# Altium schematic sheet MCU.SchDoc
size 558 x 431 mm; DocumentNumber: 4; SheetNumber: 4; SheetTotal: 4; PageSetup: Record=PageOptions|CenterHorizontal=True|CenterVertical=True|PrintScale=0.89|XCorrection=1.00|YCorrection=1.00|PrintKind=0|BorderSize=5000000|LeftOffset=0|BottomOffset=0|Orientation=2|PaperLength=1000|PaperWidth=1000|Scale=100|PaperSource=15|PrintQuality=600|MediaType=1|DitherType=10|PaperKind=A4|PrintScaleMode=1
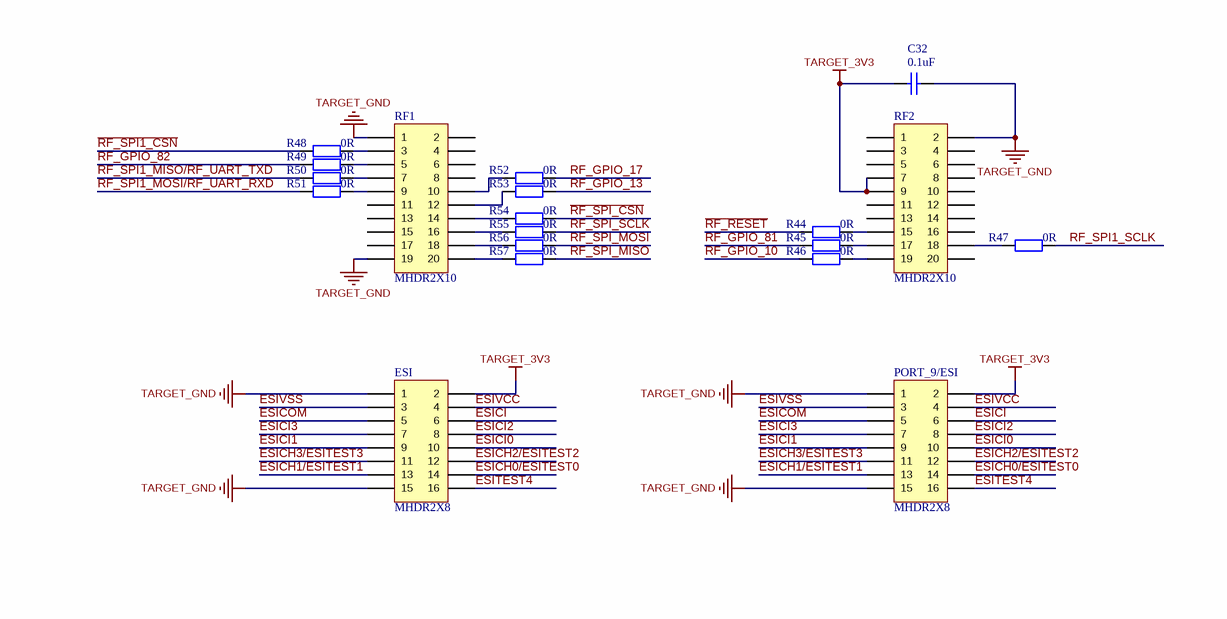
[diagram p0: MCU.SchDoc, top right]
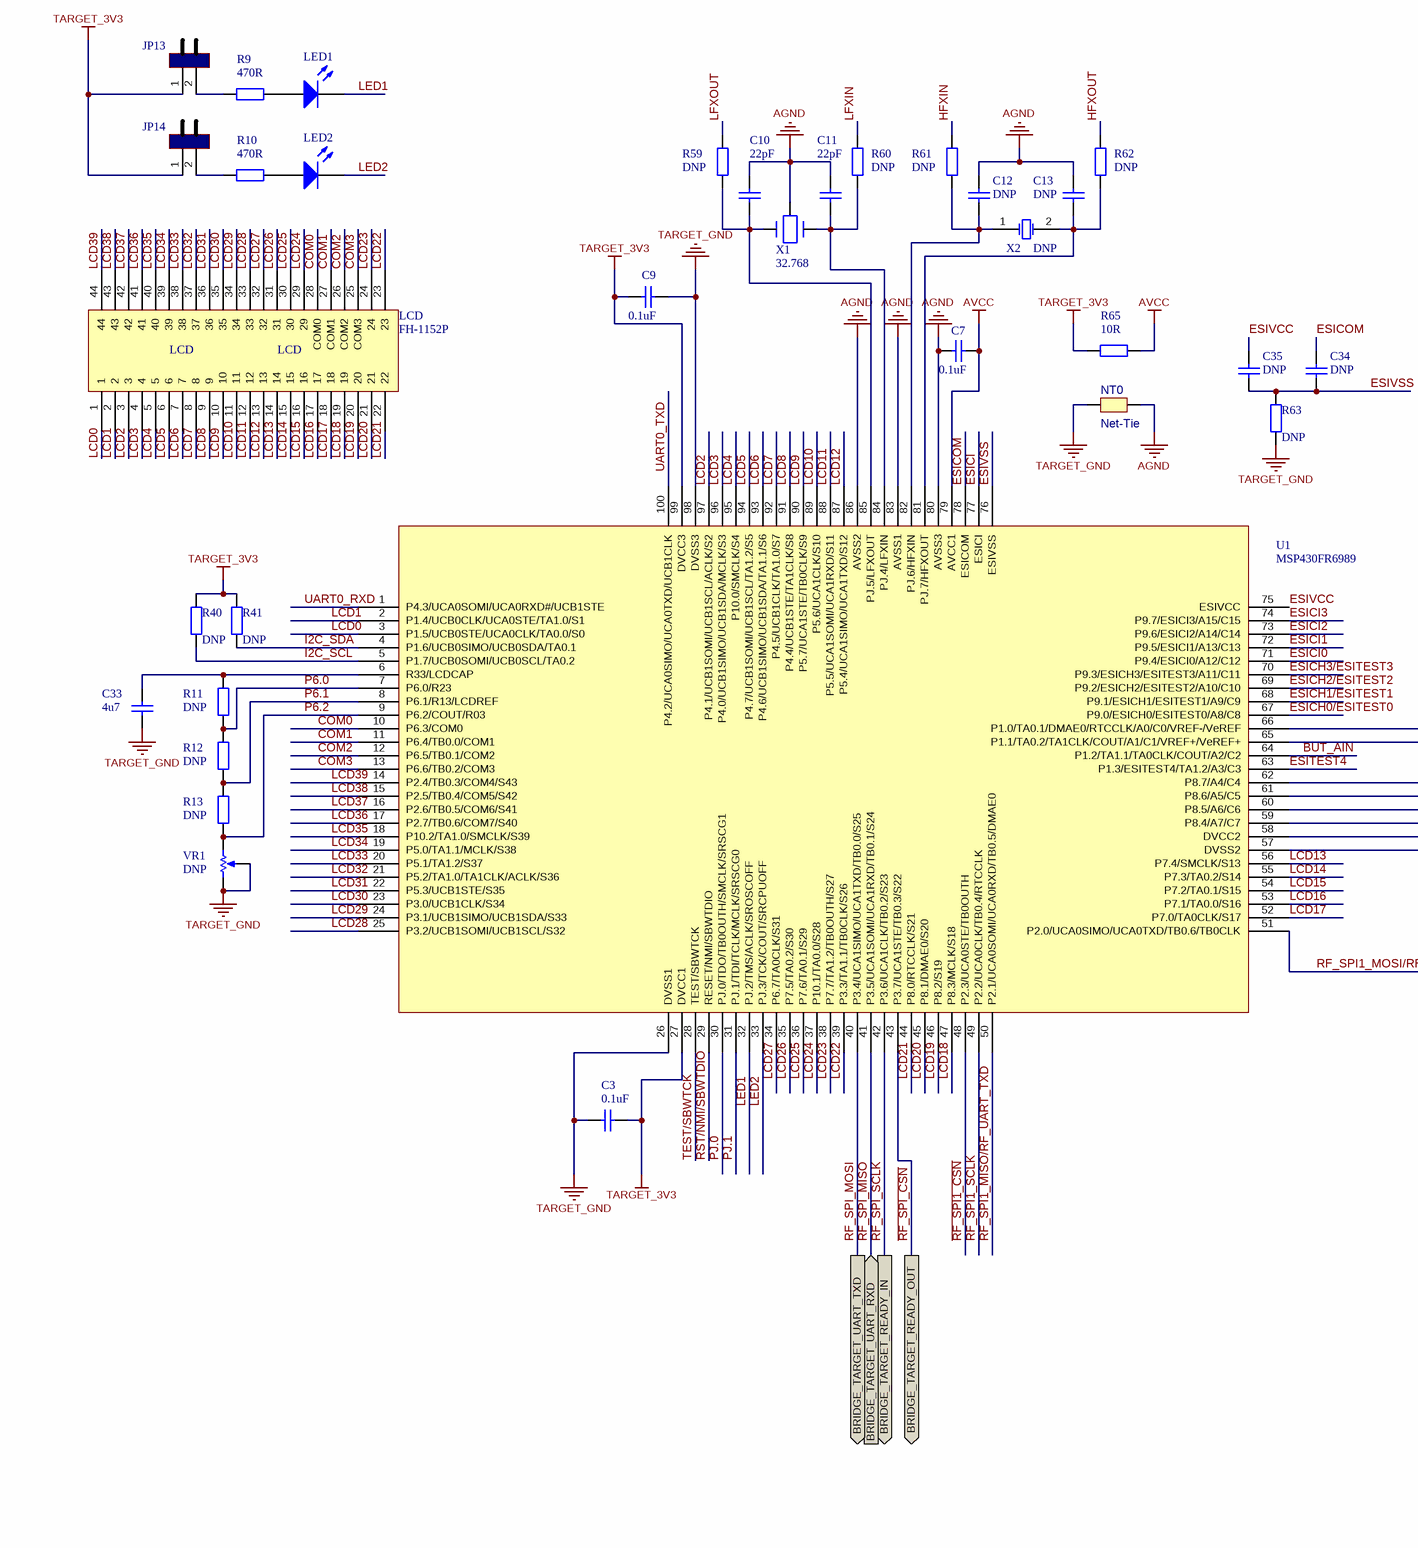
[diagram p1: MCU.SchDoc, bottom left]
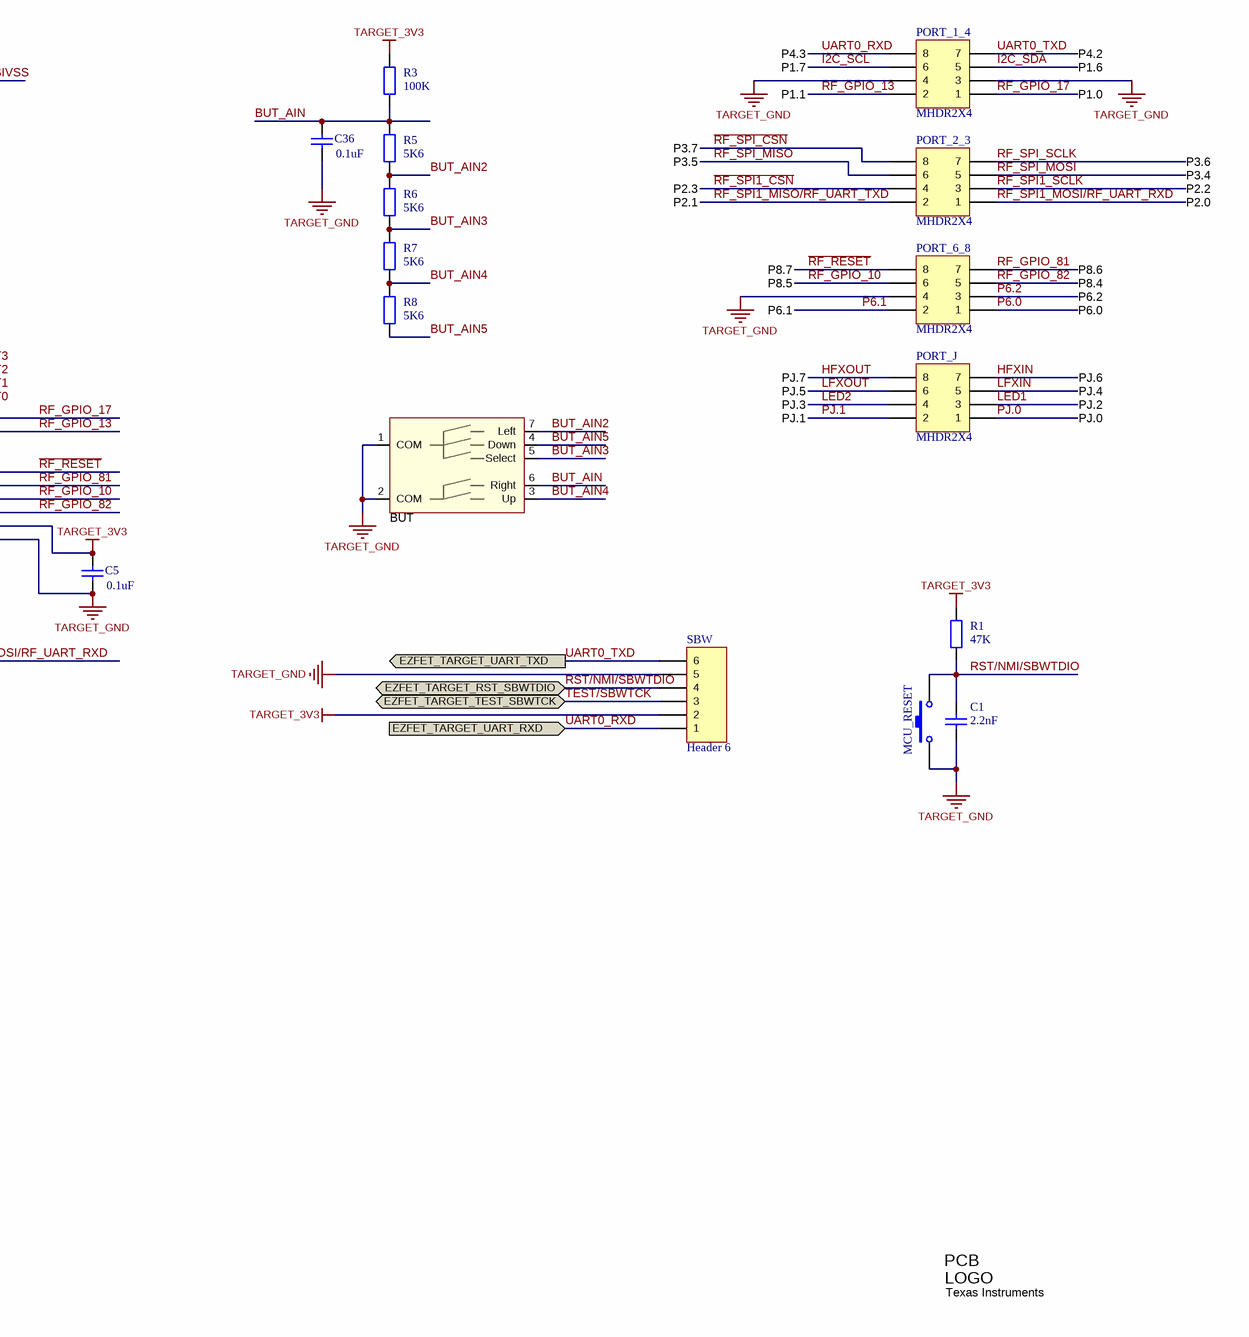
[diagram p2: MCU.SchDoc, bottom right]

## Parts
BUT  Used in BOM report  [TPA511GLFS]  (value not drawn)
C1  value 2.2nF  [0402]
C3  value 0.1uF  [0402]
C5  value 0.1uF  [0402]
C7  value 0.1uF  [0402]
C9  value 0.1uF  [0402]
C10  value 22pF  [0402]
C11  value 22pF  [0402]
C12  value DNP  [0402]
C13  value DNP  [0402]
C32  value 0.1uF  [0402]
C33  value 4u7  [0805]
C34  value DNP  [0402]
C35  value DNP  [0402]
C36  value 0.1uF  [0402]
ESI  MHDR2X8  [HDR2X8]
JP13  JUMPER  [HDR1X2]  (value not drawn)
JP14  JUMPER  [HDR1X2]  (value not drawn)
LCD  FH-1152P  [FH-1152P]
LED1  (no value)  [LED_LTST-C190]
LED2  (no value)  [LED_LTST-C190]
Logo  Texas Instruments  [TI_Stacked_Overlay_Medium]  (no BOM)
MCU_RESET  (no value)  [B3U-1000P]
NT0  Net-Tie  [Net-Tie_20milWide_60milLong]  (net tie, no BOM)
PORT_1_4  MHDR2X4  [HDR2X4]
PORT_2_3  MHDR2X4  [HDR2X4]
PORT_6_8  MHDR2X4  [HDR2X4]
PORT_9/ESI  MHDR2X8  [HDR2X8]
PORT_J  MHDR2X4  [HDR2X4]
R1  value 47K  [0402]
R3  value 100K  [0402]
R5  value 5K6  [0402]
R6  value 5K6  [0402]
R7  value 5K6  [0402]
R8  value 5K6  [0402]
R9  value 470R  [0402]
R10  value 470R  [0402]
R11  value DNP  [0402]
R12  value DNP  [0402]
R13  value DNP  [0402]
R40  value DNP  [0402]
R41  value DNP  [0402]
R44  value 0R  [0402]
R45  value 0R  [0402]
R46  value 0R  [0402]
R47  value 0R  [0402]
R48  value 0R  [0402]
R49  value 0R  [0402]
R50  value 0R  [0402]
R51  value 0R  [0402]
R52  value 0R  [0402]
R53  value 0R  [0402]
R54  value 0R  [0402]
R55  value 0R  [0402]
R56  value 0R  [0402]
R57  value 0R  [0402]
R59  value DNP  [0402]
R60  value DNP  [0402]
R61  value DNP  [0402]
R62  value DNP  [0402]
R63  value DNP  [0402]
R65  value 10R  [0402]
RF1  MHDR2X10  [TFM-110-02-SM-D-A-K]
RF2  MHDR2X10  [TFM-110-02-SM-D-A-K]
SBW  Header 6  [CONN_SMS-106-01-G-S]
U1  MSP430FR6989  [MSP430FR6989]
VR1  value DNP  [VR-3150]
X1  32.768  [01-CR3-1B]
X2  DNP  [ABM3]

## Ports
BRIDGE_TARGET_READY_IN (out), BRIDGE_TARGET_READY_OUT (out), BRIDGE_TARGET_UART_RXD (in), BRIDGE_TARGET_UART_TXD (out), EZFET_TARGET_RST_SBWTDIO (bidir), EZFET_TARGET_TEST_SBWTCK (bidir), EZFET_TARGET_UART_RXD (in), EZFET_TARGET_UART_TXD (out)

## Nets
AGND: C7.1 C10.1 C11.2 C12.1 C13.2 NT0.1 U1.80(AVSS3) U1.83(AVSS1) U1.86(AVSS2) X1.3
AVCC: C7.2 R65.1 U1.79(AVCC1)
TARGET_3V3: C3.2 C5.1 C9.2 C32.1 ESI.2 JP13.1 JP14.1 PORT_9/ESI.2 R1.2 R3.2 R40.2 R41.2 R65.2 RF2.7 RF2.9 SBW.2 U1.27(DVCC1) U1.58(DVCC2) U1.99(DVCC3)
TARGET_GND: BUT.1(COM) BUT.2(COM) C1.1 C3.1 C5.2 C9.1 C32.2 C33.1 C36.2 ESI.1 ESI.15 MCU_RESET.1 NT0.2 PORT_1_4.3 PORT_1_4.4 PORT_6_8.4 PORT_9/ESI.1 PORT_9/ESI.15 R63.1 RF1.1 RF1.19 RF2.2 SBW.5 U1.26(DVSS1) U1.57(DVSS2) U1.98(DVSS3) VR1.1(TOP) VR1.3(TAP)
~{RF_RESET}: PORT_6_8.8 R44.2 U1.62(P8.7/A4/C4)
~{RF_SPI1_CSN}: PORT_2_3.4 R48.2 U1.48(P2.3/UCA0STE/TB0OUTH)
~{RF_SPI_CSN}: PORT_2_3.8 R54.2 U1.43(P3.7/UCA1STE/TB0.3/S22) ; port BRIDGE_TARGET_READY_OUT
BUT_AIN: BUT.6(Right) C36.1 R3.1 R5.2 U1.64(P1.2/TA1.1/TA0CLK/COUT/A2/C2)
BUT_AIN2: BUT.7(Left) R5.1 R6.2
BUT_AIN3: BUT.5(Select) R6.1 R7.2
BUT_AIN4: BUT.3(Up) R7.1 R8.2
BUT_AIN5: BUT.4(Down) R8.1
COM0: LCD.28(COM0) U1.10(P6.3/COM0)
COM1: LCD.27(COM1) U1.11(P6.4/TB0.0/COM1)
COM2: LCD.26(COM2) U1.12(P6.5/TB0.1/COM2)
COM3: LCD.25(COM3) U1.13(P6.6/TB0.2/COM3)
ESICH0/ESITEST0: ESI.14 PORT_9/ESI.14 U1.67(P9.0/ESICH0/ESITEST0/A8/C8)
ESICH1/ESITEST1: ESI.13 PORT_9/ESI.13 U1.68(P9.1/ESICH1/ESITEST1/A9/C9)
ESICH2/ESITEST2: ESI.12 PORT_9/ESI.12 U1.69(P9.2/ESICH2/ESITEST2/A10/C10)
ESICH3/ESITEST3: ESI.11 PORT_9/ESI.11 U1.70(P9.3/ESICH3/ESITEST3/A11/C11)
ESICI: ESI.6 PORT_9/ESI.6 U1.77(ESICI)
ESICI0: ESI.10 PORT_9/ESI.10 U1.71(P9.4/ESICI0/A12/C12)
ESICI1: ESI.9 PORT_9/ESI.9 U1.72(P9.5/ESICI1/A13/C13)
ESICI2: ESI.8 PORT_9/ESI.8 U1.73(P9.6/ESICI2/A14/C14)
ESICI3: ESI.7 PORT_9/ESI.7 U1.74(P9.7/ESICI3/A15/C15)
ESICOM: C34.1 ESI.5 PORT_9/ESI.5 U1.78(ESICOM)
ESITEST4: ESI.16 PORT_9/ESI.16 U1.63(P1.3/ESITEST4/TA1.2/A3/C3)
ESIVCC: C35.2 ESI.4 PORT_9/ESI.4 U1.75(ESIVCC)
ESIVSS: C34.2 C35.1 ESI.3 PORT_9/ESI.3 R63.2 U1.76(ESIVSS)
HFXIN: PORT_J.7 R61.1
HFXOUT: PORT_J.8 R62.1
I2C_SCL: PORT_1_4.6 R40.1 U1.5(P1.7/UCB0SOMI/UCB0SCL/TA0.2)
I2C_SDA: PORT_1_4.5 R41.1 U1.4(P1.6/UCB0SIMO/UCB0SDA/TA0.1)
LCD0: LCD.1 U1.3(P1.5/UCB0STE/UCA0CLK/TA0.0/S0)
LCD1: LCD.2 U1.2(P1.4/UCB0CLK/UCA0STE/TA1.0/S1)
LCD2: LCD.3 U1.97(P4.1/UCB1SOMI/UCB1SCL/ACLK/S2)
LCD3: LCD.4 U1.96(P4.0/UCB1SIMO/UCB1SDA/MCLK/S3)
LCD4: LCD.5 U1.95(P10.0/SMCLK/S4)
LCD5: LCD.6 U1.94(P4.7/UCB1SOMI/UCB1SCL/TA1.2/S5)
LCD6: LCD.7 U1.93(P4.6/UCB1SIMO/UCB1SDA/TA1.1/S6)
LCD7: LCD.8 U1.92(P4.5/UCB1CLK/TA1.0/S7)
LCD8: LCD.9 U1.91(P4.4/UCB1STE/TA1CLK/S8)
LCD9: LCD.10 U1.90(P5.7/UCA1STE/TB0CLK/S9)
LCD10: LCD.11 U1.89(P5.6/UCA1CLK/S10)
LCD11: LCD.12 U1.88(P5.5/UCA1SOMI/UCA1RXD/S11)
LCD12: LCD.13 U1.87(P5.4/UCA1SIMO/UCA1TXD/S12)
LCD13: LCD.14 U1.56(P7.4/SMCLK/S13)
LCD14: LCD.15 U1.55(P7.3/TA0.2/S14)
LCD15: LCD.16 U1.54(P7.2/TA0.1/S15)
LCD16: LCD.17 U1.53(P7.1/TA0.0/S16)
LCD17: LCD.18 U1.52(P7.0/TA0CLK/S17)
LCD18: LCD.19 U1.47(P8.3/MCLK/S18)
LCD19: LCD.20 U1.46(P8.2/S19)
LCD20: LCD.21 U1.45(P8.1/DMAE0/S20)
LCD21: LCD.22 U1.44(P8.0/RTCCLK/S21)
LCD22: LCD.23 U1.39(P3.3/TA1.1/TB0CLK/S26)
LCD23: LCD.24 U1.38(P7.7/TA1.2/TB0OUTH/S27)
LCD24: LCD.29 U1.37(P10.1/TA0.0/S28)
LCD25: LCD.30 U1.36(P7.6/TA0.1/S29)
LCD26: LCD.31 U1.35(P7.5/TA0.2/S30)
LCD27: LCD.32 U1.34(P6.7/TA0CLK/S31)
LCD28: LCD.33 U1.25(P3.2/UCB1SOMI/UCB1SCL/S32)
LCD29: LCD.34 U1.24(P3.1/UCB1SIMO/UCB1SDA/S33)
LCD30: LCD.35 U1.23(P3.0/UCB1CLK/S34)
LCD31: LCD.36 U1.22(P5.3/UCB1STE/S35)
LCD32: LCD.37 U1.21(P5.2/TA1.0/TA1CLK/ACLK/S36)
LCD33: LCD.38 U1.20(P5.1/TA1.2/S37)
LCD34: LCD.39 U1.19(P5.0/TA1.1/MCLK/S38)
LCD35: LCD.40 U1.18(P10.2/TA1.0/SMCLK/S39)
LCD36: LCD.41 U1.17(P2.7/TB0.6/COM7/S40)
LCD37: LCD.42 U1.16(P2.6/TB0.5/COM6/S41)
LCD38: LCD.43 U1.15(P2.5/TB0.4/COM5/S42)
LCD39: LCD.44 U1.14(P2.4/TB0.3/COM4/S43)
LED1: LED1.2(K) PORT_J.3 U1.32(PJ.2/TMS/ACLK/SROSCOFF)
LED2: LED2.2(K) PORT_J.4 U1.33(PJ.3/TCK/COUT/SRCPUOFF)
LFXIN: PORT_J.5 R60.2
LFXOUT: PORT_J.6 R59.2
P6.0: PORT_6_8.1 R11.1 R12.2 U1.7(P6.0/R23)
P6.1: PORT_6_8.2 R12.1 R13.2 U1.8(P6.1/R13/LCDREF)
P6.2: PORT_6_8.3 R13.1 U1.9(P6.2/COUT/R03) VR1.2(BOT)
PJ.0: PORT_J.1 U1.30(PJ.0/TDO/TB0OUTH/SMCLK/SRSCG1)
PJ.1: PORT_J.2 U1.31(PJ.1/TDI/TCLK/MCLK/SRSCG0)
RF_GPIO_10: PORT_6_8.6 R46.2 U1.60(P8.5/A6/C6)
RF_GPIO_13: PORT_1_4.2 R53.2 U1.65(P1.1/TA0.2/TA1CLK/COUT/A1/C1/VREF+/VeREF+)
RF_GPIO_17: PORT_1_4.1 R52.2 U1.66(P1.0/TA0.1/DMAE0/RTCCLK/A0/C0/VREF-/VeREF)
RF_GPIO_81: PORT_6_8.7 R45.2 U1.61(P8.6/A5/C5)
RF_GPIO_82: PORT_6_8.5 R49.2 U1.59(P8.4/A7/C7)
RF_SPI1_MISO/RF_UART_TXD: PORT_2_3.2 R50.2 U1.50(P2.1/UCA0SOMI/UCA0RXD/TB0.5/DMAE0)
RF_SPI1_MOSI/RF_UART_RXD: PORT_2_3.1 R51.2 U1.51(P2.0/UCA0SIMO/UCA0TXD/TB0.6/TB0CLK)
RF_SPI1_SCLK: PORT_2_3.3 R47.2 U1.49(P2.2/UCA0CLK/TB0.4/RTCCLK)
RF_SPI_MISO: PORT_2_3.6 R57.2 U1.41(P3.5/UCA1SOMI/UCA1RXD/TB0.1/S24) ; port BRIDGE_TARGET_UART_RXD
RF_SPI_MOSI: PORT_2_3.5 R56.2 U1.40(P3.4/UCA1SIMO/UCA1TXD/TB0.0/S25) ; port BRIDGE_TARGET_UART_TXD
RF_SPI_SCLK: PORT_2_3.7 R55.2 U1.42(P3.6/UCA1CLK/TB0.2/S23) ; port BRIDGE_TARGET_READY_IN
RST/NMI/SBWTDIO: C1.2 MCU_RESET.2 R1.1 SBW.4 U1.29(RESET/NMI/SBWTDIO) ; port EZFET_TARGET_RST_SBWTDIO
TEST/SBWTCK: SBW.3 U1.28(TEST/SBWTCK) ; port EZFET_TARGET_TEST_SBWTCK
UART0_RXD: PORT_1_4.8 SBW.1 U1.1(P4.3/UCA0SOMI/UCA0RXD#/UCB1STE) ; port EZFET_TARGET_UART_RXD
UART0_TXD: PORT_1_4.7 SBW.6 U1.100(P4.2/UCA0SIMO/UCA0TXD/UCB1CLK) ; port EZFET_TARGET_UART_TXD
NetC10_2: C10.2 R59.1 U1.85(PJ.5/LFXOUT) X1.1
NetC11_1: C11.1 R60.1 U1.84(PJ.4/LFXIN) X1.2
NetC12_2: C12.2 R61.2 U1.82(PJ.6/HFXIN) X2.1(OSC1)
NetC13_1: C13.1 R62.2 U1.81(PJ.7/HFXOUT) X2.2(OSC2)
NetC33_2: C33.2 R11.2 U1.6(R33/LCDCAP)
NetJP13_2: JP13.2 R9.1
NetJP14_2: JP14.2 R10.1
NetLED1_1: LED1.1(A) R9.2
NetLED2_1: LED2.1(A) R10.2
NetR44_1: R44.1 RF2.15
NetR45_1: R45.1 RF2.17
NetR46_1: R46.1 RF2.19
NetR47_1: R47.1 RF2.18
NetR48_1: R48.1 RF1.3
NetR49_1: R49.1 RF1.5
NetR50_1: R50.1 RF1.7
NetR51_1: R51.1 RF1.9
NetR52_1: R52.1 RF1.10
NetR53_1: R53.1 RF1.12
NetR54_1: R54.1 RF1.14
NetR55_1: R55.1 RF1.16
NetR56_1: R56.1 RF1.18
NetR57_1: R57.1 RF1.20

Not connected (* = marked no-connect by the designer): RF1 2 4 6 8 11 13 15 17; RF2 1 3 4 5 6 8 10 11 12 13 14 16 20

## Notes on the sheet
- P4.3
- P1.7
- P1.1
- P1.0
- P1.6
- P4.2
- P3.5
- P3.7
- P3.4
- P3.6
- P2.1
- P2.3
- P2.0
- P2.2
- P6.1
- P8.5
- P8.7
- P6.0
- P6.2
- P8.4
- P8.6
- PJ.7
- PJ.6
- PJ.1
- PJ.3
- PJ.5
- PJ.0
- PJ.2
- PJ.4

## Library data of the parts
BUT = Nav Button: SymbolVersion: use current date i.e. 2008-05-20; SymbolCreator: Use a-id; CompType: Used in some BOM reports.  Useful for finding later.; U/M: EA, IN, or GM
C1 C3 C5 C7 C9-C13 C32-C36 = Cap: Capacitor
ESI PORT_9/ESI = MHDR2X8: Header, 8-Pin, Dual row
LED1 LED2 = LED2: Typical RED, GREEN, YELLOW, AMBER GaAs LED
Logo = TI_Logo: Texas Instrument Corporate Signature; SymbolCreator: a0412235
MCU_RESET = SW-PB: Switch
NT0 = Net-Tie: Single point connection between nets.; SymbolCreator: codlsc
PORT_1_4 PORT_2_3 PORT_6_8 PORT_J = MHDR2X4: Header, 4-Pin, Dual row
R1 R3 R5-R13 R40 R41 R44-R57 R59-R63 R65 = Res2: Resistor
RF1 RF2 = MHDR2X10: Header, 10-Pin, Dual row
SBW = Header 6: Header, 6-Pin
U1 = MSP430FR698XPZ
VR1 = RPot: Potentiometer; Sim Note: Enter the Resistance value and the set point into parameter fields.; Set Position: 0.5
X1 = XTAL3
X2 = XTAL: Crystal Oscillator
